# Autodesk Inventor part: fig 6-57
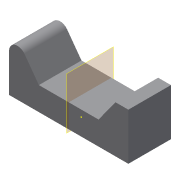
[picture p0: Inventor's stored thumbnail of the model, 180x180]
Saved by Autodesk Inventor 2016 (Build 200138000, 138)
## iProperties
Created: 2011-07
Part Number: fig 6-57
Material: Generic
Document SubType Name: Modeling
Designer: CadCim
Density: 1 g/cm^3
Appearance: Default
Author: CadCim
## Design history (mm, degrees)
sketch "Sketch1"
  geometry: 1 further point
sketch "Sketch2"
  geometry: L1 (3, -4)-(17, -4); L2 (17, -4)-(17, 7); L3 (17, 7)-(14, 7); L4 (14, 7)-(10, 1.5); L5 (10, 1.5)-(3, 1.5); L6 (3, -4)-(-11, -4); L7 (-11, -4)-(-11, 7); L8 (-11, 7)-(-8, 7); L9 (-8, 7)-(-4, 1.5); L10 (-4, 1.5)-(3, 1.5); 1 further point
  constraints: 20 end point, 2 parallel, 1 perpendicular
extrude "Extrusion1" new body sketch "Sketch2" distance "d0" = 10; taper "d1" = 0 deg
fillet "Fillet1" dims "d2" = 2
workplane "Work Plane1"
body "Solid1"
